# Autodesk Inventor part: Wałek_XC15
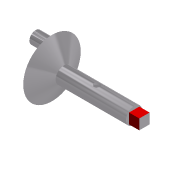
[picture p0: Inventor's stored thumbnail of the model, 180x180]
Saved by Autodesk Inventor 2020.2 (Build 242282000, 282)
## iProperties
Created: 2000-05
Part Number: Wałek_XC15
Document SubType Name: Modeling
Designer: F.Stasiak
Stock Number: Wałek_XC15
Density: 1 g/cm^3
Material: Default
Appearance: Aluminium (polerowane)
Manager: www.cadconsulting.pl
Company: Fabian Stasiak CAD Consulting
Control State: 0
Master: False
Checked Out: False
Shininess: 0.0
Density: 0.0
Volumn: 0.0
Area: 0.0
PropertySet Name: Model Information
Author: F.Stasiak
Subject: Zbiór ćwiczeń. Autodesk Inventor 2020. Kurs podstawowy
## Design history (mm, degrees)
node "Base1"
node "Bryła1"
node "Korpusy bryłowe"
node "Korpusy powierzchniowe"
